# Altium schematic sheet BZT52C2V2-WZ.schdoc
size 127 x 101 mm
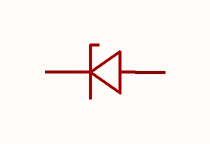
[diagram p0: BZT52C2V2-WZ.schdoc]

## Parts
D?  bzt52c2v2  [SOD-123_L2.7-W1.6-LS3.7-RD-1]  (value not drawn)

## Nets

Not connected (* = marked no-connect by the designer): D? 1(K) 2(A)

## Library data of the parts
D? = bzt52c2v2: 二极管配置:1个独立式;稳压值(标称值):2.2V;稳压值(范围):2.09V~2.31V;耗散功率(Pd):500mW;; Manufacturer: MDD(辰达半导体); Symbol: BZT52C2V2-WZ; AddInBom: yes; ModelId: 528459655f7d4601a76356f3191c812b; ModelTransform: 151.575,66.929,0,0,0,0,0,0,0; Diode Configuration: 1个独立式; Zener Voltage(Nom): 2.2V; Reverse Leakage Current (Ir): 120uA; Pd - Power Dissipation: 500mW; Impedance(Zzt): 100Ω; Tolerance: ±5%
